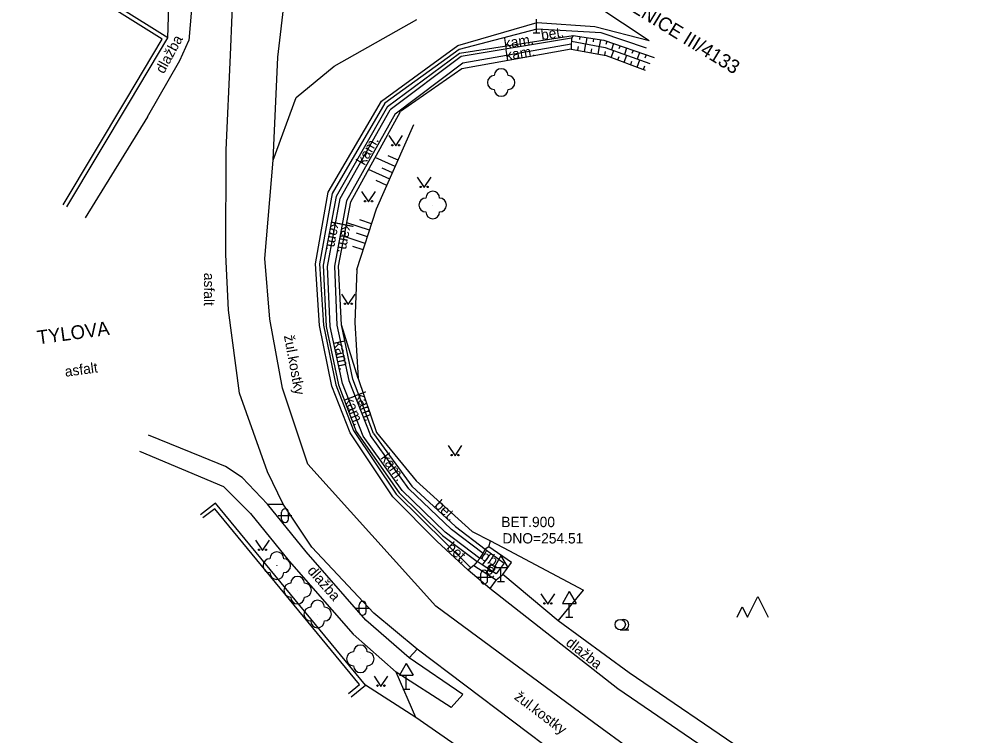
# Model space of a CAD drawing. Extents: x -621516 to -621304, y -1175233 to -1174899.
# Drawn here: x -621495.1 to -621425.3, y -1175001.6 to -1174949.6 of the extents above; entities that cross this region are included whole.
import ezdxf

# ---------------------------------------------------------------- set-up
doc = ezdxf.new("R2010")
doc.units = 0
for name, color, linetype in [('Doplňkové značky', 7, 'Continuous'), ('Názvy', 7, 'Continuous'), ('Pomocné popisy', 7, 'Continuous'), ('Rozhraní ploch', 7, 'Continuous'), ('Výškopis', 7, 'Continuous'), ('Zeleň', 7, 'Continuous'), ('Značky kultur', 7, 'Continuous')]:
    doc.layers.add(name, color=color, linetype=linetype)

msp = doc.modelspace()

# ---------------------------------------------------------------- linework, layer by layer
at = {"layer": 'Doplňkové značky'}
for p, q in [((-621457.53, -1174950.56), (-621457.53, -1174949.56)), ((-621457.78, -1174950.56), (-621457.28, -1174950.56)), ((-621461, -1174987.88), (-621461.25, -1174988.04)), ((-621461.03, -1174988.61), (-621460.83, -1174988.35)), ((-621460.11, -1174988.514), (-621460.61, -1174989.38)), ((-621460.11, -1174988.514), (-621459.61, -1174989.38)), ((-621461.84, -1174988.94), (-621462.08, -1174989.22)), ((-621461.31, -1174988.97), (-621461.47, -1174989.18)), ((-621461.03, -1174988.61), (-621461.31, -1174988.97)), ((-621460.61, -1174989.38), (-621459.61, -1174989.38)), ((-621460.11, -1174990.38), (-621460.11, -1174989.38)), ((-621460.36, -1174990.38), (-621459.86, -1174990.38)), ((-621455.15, -1174991.124), (-621455.65, -1174991.99)), ((-621455.15, -1174991.124), (-621454.65, -1174991.99)), ((-621455.65, -1174991.99), (-621454.65, -1174991.99)), ((-621455.15, -1174992.99), (-621455.15, -1174991.99)), ((-621455.4, -1174992.99), (-621454.9, -1174992.99)), ((-621466.99, -1174996.334), (-621467.49, -1174997.2)), ((-621466.99, -1174996.334), (-621466.49, -1174997.2)), ((-621467.49, -1174997.2), (-621466.49, -1174997.2)), ((-621466.99, -1174998.2), (-621466.99, -1174997.2)), ((-621467.24, -1174998.2), (-621466.74, -1174998.2))]:
    msp.add_line(p, q, dxfattribs=at)
for points in [[(-621491.9, -1174963.04), (-621487.347, -1174955.446), (-621484.708, -1174951.028), (-621495.1, -1174944.51)], [(-621491.64, -1174963.19), (-621487.09, -1174955.6), (-621484.3, -1174950.93), (-621494.94, -1174944.26)], [(-621449.54, -1174951.67), (-621452.83, -1174950.55), (-621457.51, -1174950.3), (-621463.15, -1174951.76), (-621468.54, -1174955.66), (-621472.37, -1174962.23), (-621473.28, -1174967.34), (-621472.99, -1174971.77), (-621472.11, -1174976.12), (-621470.82, -1174979.42)], [(-621470.58, -1174967.75), (-621470.73, -1174971.6), (-621470.48, -1174975.65), (-621469.14, -1174979.58)], [(-621470.82, -1174979.42), (-621467.73, -1174984.05), (-621462.29, -1174989.4)], [(-621469.14, -1174979.58), (-621466.28, -1174983.08), (-621462.21, -1174986.76), (-621460.88, -1174987.44), (-621459.54, -1174988.13), (-621454.11, -1174991.03)], [(-621470.99, -1174998.75), (-621469.95, -1174997.92), (-621480.84, -1174984.7), (-621481.94, -1174985.54)], [(-621471.177, -1174998.516), (-621470.375, -1174997.876), (-621480.888, -1174985.114), (-621481.758, -1174985.778)], [(-621462.08, -1174989.22), (-621460.45, -1174990.28), (-621459.98, -1174989.87), (-621459.35, -1174989), (-621461, -1174987.88)], [(-621461.84, -1174988.94), (-621461.65, -1174988.71), (-621461.41, -1174988.35), (-621461.25, -1174988.04)], [(-621461.25, -1174988.04), (-621459.88, -1174989.05), (-621460.45, -1174989.84), (-621461.47, -1174989.18), (-621461.84, -1174988.94)], [(-621442.96, -1174992.98), (-621442.585, -1174992.23), (-621442.21, -1174992.98), (-621441.46, -1174991.48), (-621440.71, -1174992.98)]]:
    msp.add_lwpolyline(points, dxfattribs=at)
for radius in [0.25, 0.0005]:
    msp.add_circle((-621460.821, -1174989.44), radius, dxfattribs=at)
at = {"layer": 'Rozhraní ploch'}
for p, q in [((-621482.34, -1174945.57), (-621482.77, -1174951.11)), ((-621476.31, -1174952.33), (-621475.53, -1174945.49)), ((-621485.78, -1174956.65), (-621490.31, -1174964)), ((-621470.48, -1174975.65), (-621471.69, -1174971.75)), ((-621480.23, -1174983.52), (-621486.35, -1174980.96)), ((-621477.06, -1174984.77), (-621478.91, -1174982.84)), ((-621475.92, -1174984.77), (-621477.07, -1174982.42)), ((-621477.06, -1174984.77), (-621475.92, -1174984.77)), ((-621461, -1174987.88), (-621460.88, -1174987.44)), ((-621460.93, -1174990.89), (-621462.5, -1174989.57)), ((-621460.45, -1174990.28), (-621460.93, -1174990.89)), ((-621463.74, -1174999.54), (-621467.73, -1174996.96)), ((-621462.87, -1174998.6), (-621463.74, -1174999.54))]:
    msp.add_line(p, q, dxfattribs=at)
for points in [[(-621479.75, -1174952.18), (-621479.51, -1174946.26), (-621480.84, -1174934.18), (-621484.87, -1174927.59)], [(-621484.87, -1174927.59), (-621471.01, -1174936.75), (-621449.34, -1174951.12)], [(-621484.3, -1174950.93), (-621484.13, -1174945.51), (-621484.06, -1174943.5), (-621493.37, -1174937.91)], [(-621476.65, -1174959.8), (-621474.99, -1174955.26), (-621472.23, -1174952.99), (-621466.22, -1174949.59)], [(-621468.8, -1174955.51), (-621463.24, -1174951.47), (-621457.48, -1174949.82), (-621453.29, -1174950.11), (-621449.34, -1174951.12)], [(-621468.36, -1174955.92), (-621463.13, -1174952.03), (-621454.87, -1174950.75)], [(-621454.87, -1174950.75), (-621454.98, -1174950.96), (-621455, -1174951.16), (-621455.01, -1174951.37), (-621455.02, -1174951.74)], [(-621485.78, -1174956.65), (-621483.43, -1174952.57), (-621482.77, -1174951.11)], [(-621454.98, -1174950.96), (-621463, -1174952.29), (-621468.16, -1174956.14)], [(-621467.79, -1174956.45), (-621462.87, -1174952.73), (-621455.01, -1174951.37)], [(-621477.07, -1174982.42), (-621479.09, -1174976.71), (-621479.9, -1174970.69), (-621480.09, -1174966.66), (-621480.06, -1174959.05), (-621479.75, -1174952.18)], [(-621455.02, -1174951.74), (-621462.96, -1174953.18), (-621467.4, -1174956.27)], [(-621474.13, -1174981.86), (-621475.97, -1174976.36), (-621476.9, -1174971.34), (-621477.26, -1174966.94), (-621476.65, -1174959.8), (-621476.31, -1174952.33)], [(-621471.07, -1174979.59), (-621472.4, -1174976.21), (-621473.29, -1174971.81), (-621473.58, -1174967.32), (-621472.66, -1174962.13), (-621468.8, -1174955.51)], [(-621468.36, -1174955.92), (-621472.09, -1174962.44), (-621473.03, -1174967.42), (-621472.81, -1174971.87), (-621471.91, -1174976.11), (-621470.63, -1174979.5)], [(-621470.12, -1174979.85), (-621471.62, -1174976.02), (-621472.51, -1174971.87), (-621472.71, -1174967.52), (-621471.8, -1174962.58), (-621468.16, -1174956.14)], [(-621467.79, -1174956.45), (-621471.32, -1174962.75), (-621472.21, -1174967.5), (-621472.04, -1174971.79), (-621471.17, -1174975.81), (-621469.59, -1174979.79)], [(-621471.69, -1174971.75), (-621471.92, -1174967.5), (-621471.02, -1174962.83), (-621467.4, -1174956.27)], [(-621469.36, -1174979.64), (-621470.88, -1174975.71), (-621471.69, -1174971.75)], [(-621470.63, -1174979.5), (-621467.51, -1174983.96), (-621464.36, -1174987.04), (-621461.84, -1174988.94)], [(-621478.91, -1174982.84), (-621480.13, -1174982.04), (-621481.84, -1174981.35), (-621485.72, -1174979.76)], [(-621462.5, -1174989.57), (-621464.77, -1174987.47), (-621467.96, -1174984.24), (-621471.07, -1174979.59)], [(-621461.65, -1174988.71), (-621464.17, -1174986.81), (-621467.28, -1174983.78), (-621470.12, -1174979.85)], [(-621461.41, -1174988.35), (-621463.7, -1174986.62), (-621466.81, -1174983.67), (-621469.59, -1174979.79)], [(-621469.36, -1174979.64), (-621466.58, -1174983.46), (-621463.42, -1174986.39), (-621461.25, -1174988.04)], [(-621429.4, -1175015.08), (-621434.02, -1175012.61), (-621445.03, -1175006.72), (-621453.4, -1175000.63), (-621464.84, -1174992.19), (-621474.13, -1174981.86)], [(-621480.23, -1174983.52), (-621478.31, -1174985.46), (-621475.5, -1174988.92), (-621470.84, -1174994.21), (-621467.73, -1174996.96)], [(-621462.87, -1174998.6), (-621466.77, -1174995.92), (-621469.92, -1174993.19), (-621474.26, -1174988.24), (-621477.06, -1174984.77)], [(-621430.6, -1175017.86), (-621436.15, -1175015.14), (-621446.55, -1175009.36), (-621455.81, -1175003.15), (-621466.19, -1174995.3), (-621469.34, -1174992.69), (-621473.84, -1174987.89), (-621475.92, -1174984.77)], [(-621462.08, -1174989.22), (-621462.29, -1174989.4), (-621462.5, -1174989.57)], [(-621427.27, -1175010.93), (-621432.07, -1175008.49), (-621442.06, -1175002.97), (-621450.8, -1174997.02), (-621455.95, -1174993.25), (-621459.98, -1174989.87)], [(-621421.41, -1175015.41), (-621427.83, -1175012.26), (-621432.62, -1175009.84), (-621442.92, -1175004.13), (-621451.63, -1174998.17), (-621460.93, -1174990.89)]]:
    msp.add_lwpolyline(points, dxfattribs=at)
at = {"layer": 'Výškopis'}
for p, q in [((-621454.376, -1174950.828), (-621454.411, -1174951.047)), ((-621454.538, -1174951.831), (-621454.486, -1174951.549)), ((-621454.047, -1174951.921), (-621453.943, -1174951.362)), ((-621453.882, -1174950.906), (-621453.954, -1174951.36)), ((-621453.388, -1174950.984), (-621453.425, -1174951.219)), ((-621453.063, -1174952.103), (-621452.961, -1174951.55)), ((-621452.894, -1174951.061), (-621452.971, -1174951.548)), ((-621452.411, -1174951.182), (-621452.487, -1174951.404)), ((-621451.938, -1174951.345), (-621452.092, -1174951.79)), ((-621451.466, -1174951.508), (-621451.543, -1174951.733)), ((-621453.555, -1174952.012), (-621453.504, -1174951.734)), ((-621452.571, -1174952.193), (-621452.522, -1174951.924)), ((-621452.098, -1174952.351), (-621451.915, -1174951.854)), ((-621451.629, -1174952.524), (-621451.537, -1174952.273)), ((-621451.16, -1174952.696), (-621450.973, -1174952.191)), ((-621450.993, -1174951.67), (-621451.15, -1174952.128)), ((-621450.52, -1174951.833), (-621450.6, -1174952.065)), ((-621450.047, -1174951.996), (-621450.209, -1174952.465)), ((-621449.575, -1174952.159), (-621449.656, -1174952.396)), ((-621450.691, -1174952.869), (-621450.597, -1174952.614)), ((-621450.221, -1174953.042), (-621450.032, -1174952.528)), ((-621449.752, -1174953.215), (-621449.657, -1174952.956)), ((-621467.786, -1174960.266), (-621469.246, -1174959.615)), ((-621467.582, -1174959.809), (-621468.293, -1174959.492)), ((-621468.192, -1174961.179), (-621469.731, -1174960.494)), ((-621467.989, -1174960.722), (-621468.739, -1174960.389)), ((-621468.396, -1174961.636), (-621469.185, -1174961.285)), ((-621469.503, -1174964.42), (-621470.361, -1174964.142)), ((-621469.657, -1174964.896), (-621471.315, -1174964.359)), ((-621469.964, -1174965.847), (-621471.505, -1174965.349)), ((-621469.81, -1174965.371), (-621470.61, -1174965.113)), ((-621470.118, -1174966.323), (-621470.859, -1174966.083)), ((-621466.3, -1175000.26), (-621467.73, -1174996.96))]:
    msp.add_line(p, q, dxfattribs=at)
for points in [[(-621454.87, -1174950.75), (-621452.65, -1174951.1), (-621448.99, -1174952.36)], [(-621455, -1174951.16), (-621452.54, -1174951.63), (-621449.3, -1174952.79)], [(-621455.02, -1174951.74), (-621452.48, -1174952.21), (-621449.63, -1174953.26)], [(-621470.58, -1174967.75), (-621469.15, -1174963.33), (-621466.43, -1174957.22)], [(-621431.22, -1175020.88), (-621437.62, -1175017.53), (-621447.85, -1175012.1), (-621459.32, -1175005.1), (-621466.3, -1175000.26)]]:
    msp.add_lwpolyline(points, dxfattribs=at)
at = {"layer": 'Zeleň'}
for p, q in [((-621455.95, -1174993.25), (-621454.11, -1174991.03)), ((-621466.19, -1174995.3), (-621466.77, -1174995.92)), ((-621466.3, -1175000.26), (-621469.95, -1174997.92))]:
    msp.add_line(p, q, dxfattribs=at)
for centre in [(-621460.1, -1174954.17), (-621465.07, -1174963.06), (-621476.39, -1174989.24), (-621474.88, -1174991.02), (-621473.43, -1174992.75), (-621470.32, -1174996)]:
    msp.add_circle(centre, 0.0005, dxfattribs=at)
for centre, start, end in [((-621460.6, -1174954.17), 89.99999, 269.99999), ((-621460.1, -1174953.67), 0, 179.99999), ((-621459.6, -1174954.17), 270, 89.99999), ((-621460.1, -1174954.67), 179.99999, 359.99999), ((-621465.07, -1174962.56), 0, 179.99999), ((-621465.57, -1174963.06), 89.99999, 269.99999), ((-621464.57, -1174963.06), 270, 89.99999), ((-621465.07, -1174963.56), 179.99999, 359.99999), ((-621476.39, -1174988.74), 0, 179.99999), ((-621476.89, -1174989.24), 89.99999, 269.99999), ((-621475.89, -1174989.24), 270, 89.99999), ((-621476.39, -1174989.74), 179.99999, 359.99999), ((-621475.38, -1174991.02), 89.99999, 269.99999), ((-621474.88, -1174990.52), 0, 179.99999), ((-621474.38, -1174991.02), 270, 89.99999), ((-621474.88, -1174991.52), 179.99999, 359.99999), ((-621473.43, -1174992.25), 0, 179.99999), ((-621473.93, -1174992.75), 89.99999, 269.99999), ((-621472.93, -1174992.75), 270, 89.99999), ((-621473.43, -1174993.25), 179.99999, 359.99999), ((-621470.82, -1174996), 89.99999, 269.99999), ((-621470.32, -1174995.5), 0, 179.99999), ((-621469.82, -1174996), 270, 89.99999), ((-621470.32, -1174996.5), 179.99999, 359.99999)]:
    msp.add_arc(centre, 0.5, start, end, dxfattribs=at)
at = {"layer": 'Značky kultur'}
for p, q in [((-621476.29, -1174985.61), (-621475.29, -1174985.61)), ((-621476.04, -1174985.86), (-621476.04, -1174985.36)), ((-621475.54, -1174985.86), (-621475.54, -1174985.36)), ((-621461.58, -1174990.32), (-621461.58, -1174989.82)), ((-621461.08, -1174990.32), (-621461.08, -1174989.82)), ((-621461.83, -1174990.07), (-621460.83, -1174990.07)), ((-621470.41, -1174992.58), (-621470.41, -1174992.08)), ((-621469.91, -1174992.58), (-621469.91, -1174992.08)), ((-621470.66, -1174992.33), (-621469.66, -1174992.33)), ((-621451.45, -1174993.895), (-621450.825, -1174993.895))]:
    msp.add_line(p, q, dxfattribs=at)
for points in [[(-621468.258, -1174958.023), (-621467.758, -1174958.773), (-621467.258, -1174958.023)], [(-621466.19, -1174961.05), (-621465.69, -1174961.8), (-621465.19, -1174961.05)], [(-621470.23, -1174962.09), (-621469.73, -1174962.84), (-621469.23, -1174962.09)], [(-621471.7, -1174969.53), (-621471.2, -1174970.28), (-621470.7, -1174969.53)], [(-621463.95, -1174980.51), (-621463.45, -1174981.26), (-621462.95, -1174980.51)], [(-621477.93, -1174987.38), (-621477.43, -1174988.13), (-621476.93, -1174987.38)], [(-621457.21, -1174991.28), (-621456.71, -1174992.03), (-621456.21, -1174991.28)], [(-621469.33, -1174997.25), (-621468.83, -1174998), (-621468.33, -1174997.25)]]:
    msp.add_lwpolyline(points, dxfattribs=at)
for centre, radius in [((-621468.008, -1174958.723), 0.05), ((-621467.508, -1174958.723), 0.05), ((-621465.94, -1174961.75), 0.05), ((-621465.44, -1174961.75), 0.05), ((-621469.98, -1174962.79), 0.05), ((-621469.48, -1174962.79), 0.05), ((-621471.45, -1174970.23), 0.05), ((-621470.95, -1174970.23), 0.05), ((-621463.7, -1174981.21), 0.05), ((-621463.2, -1174981.21), 0.05), ((-621477.68, -1174988.08), 0.05), ((-621477.18, -1174988.08), 0.05), ((-621456.96, -1174991.98), 0.05), ((-621456.46, -1174991.98), 0.05), ((-621451.45, -1174993.52), 0.375), ((-621469.08, -1174997.95), 0.05), ((-621468.58, -1174997.95), 0.05)]:
    msp.add_circle(centre, radius, dxfattribs=at)
for centre, radius, start, end in [((-621475.79, -1174985.36), 0.25, 0, 179.99999), ((-621475.79, -1174985.86), 0.25, 179.99999, 359.99999), ((-621461.33, -1174989.82), 0.25, 0, 179.99999), ((-621461.33, -1174990.32), 0.25, 179.99999, 359.99999), ((-621470.16, -1174992.08), 0.25, 0, 179.99999), ((-621470.16, -1174992.58), 0.25, 179.99999, 359.99999), ((-621451.2, -1174993.52), 0.375, 249.49437, 109.04743)]:
    msp.add_arc(centre, radius, start, end, dxfattribs=at)

# ---------------------------------------------------------------- texts
at = {"layer": 'Názvy'}
for s, rotation, p in [('SILNICE III/4133', 328.44, (-621451.72, -1174948.35)), ('TYLOVA', 7.66, (-621493.73, -1174973.18))]:
    msp.add_text(s, height=1, rotation=rotation, dxfattribs=at).set_placement(p)
at = {"layer": 'Pomocné popisy'}
for s, rotation, p in [('dlažba', 61.48382, (-621484.6, -1174953.58)), ('kam.', 8.81921, (-621459.84, -1174951.71)), ('bet.', 8.81921, (-621457.148, -1174951.094)), ('kam.', 8.81921, (-621459.74, -1174952.57)), ('kam.', 60.52411, (-621470.02, -1174960.23)), ('kam.', 259.3109, (-621472.44, -1174964.19)), ('kam.', 259.3109, (-621471.58, -1174964.36)), ('asfalt', 269.77, (-621481.68, -1174967.98)), ('žul.kostky', 280.5, (-621475.88, -1174972.56)), ('kam.', 282.1, (-621472.27, -1174972.99)), ('asfalt', 7.66, (-621491.74, -1174975.53)), ('kam.', 290.68559, (-621470.7, -1174976.79)), ('kam.', 290.68559, (-621471.5, -1174977.11)), ('kam.', 305.85, (-621468.89, -1174981.42)), ('bet.', 317.16285, (-621465, -1174984.92)), ('bet.', 317.23, (-621464.12, -1174987.99)), ('b.', 326.96378, (-621461.65, -1174988.71)), ('b.', 326.96378, (-621461.11, -1174989)), ('dlažba', 311.37706, (-621474.22, -1174989.65)), ('b.', 326.96378, (-621461.29, -1174989.69)), ('dlažba', 321.95, (-621455.46, -1174994.96)), ('žul.kostky', 322.9, (-621459.2, -1174998.88))]:
    msp.add_text(s, height=0.75, rotation=rotation, dxfattribs=at).set_placement(p)
for s, p in [('BET.900', (-621460.09, -1174986.44)), ('DNO=254.51', (-621460.01, -1174987.63))]:
    msp.add_text(s, height=0.75, dxfattribs=at).set_placement(p)

doc.saveas('drawing.dxf')
